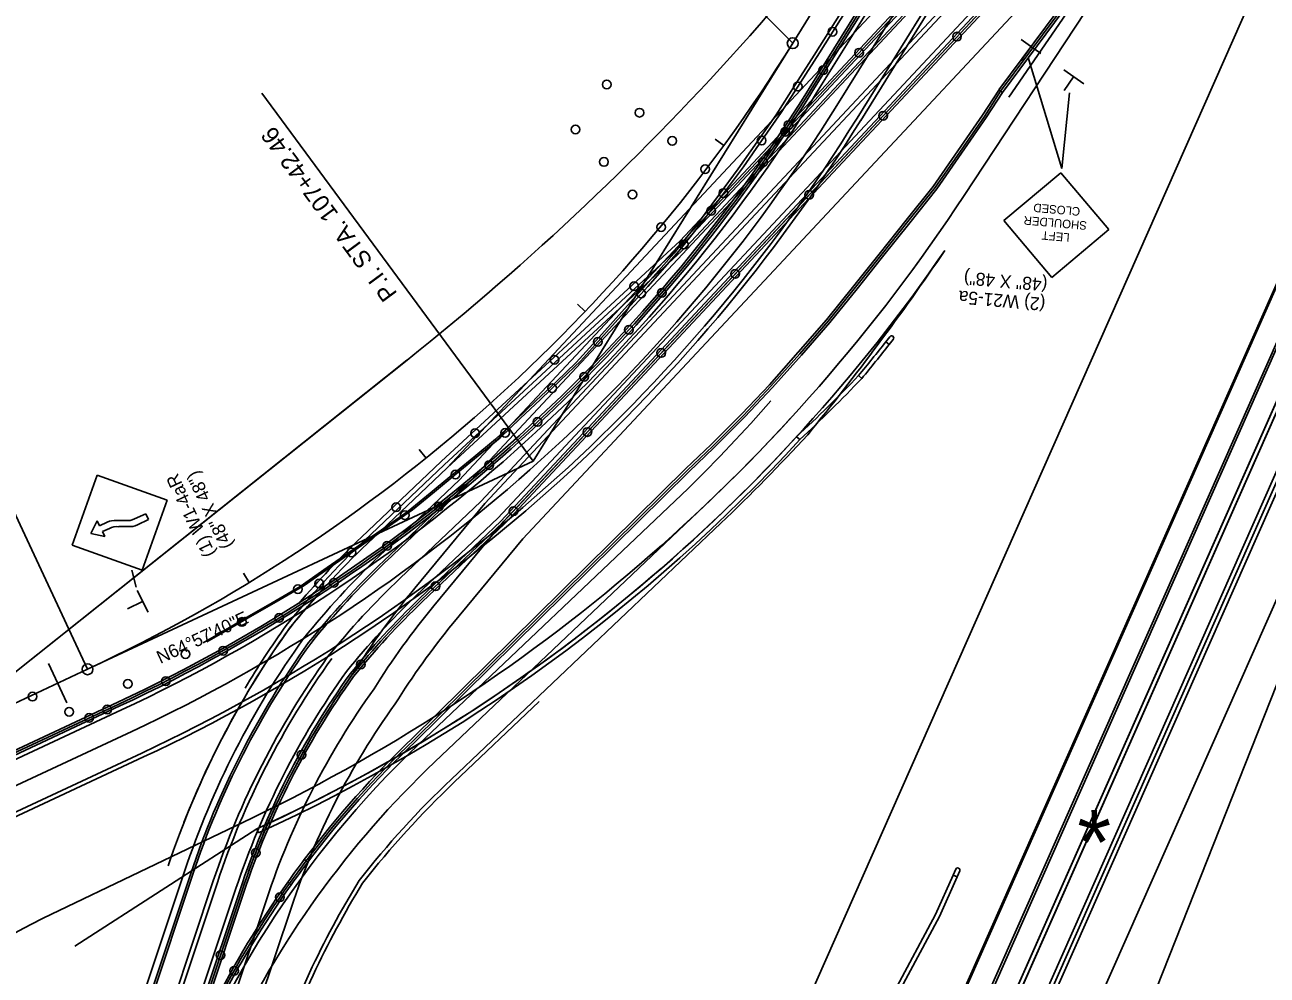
# Model space of a CAD drawing. Extents: x 659657 to 668193, y 633084 to 648639.
# Drawn here: x 661821 to 662395, y 642694 to 643133 of the extents above; entities that cross this region are included whole.
import ezdxf

# ---------------------------------------------------------------- set-up
doc = ezdxf.new("R2010")
doc.units = 0
for name, color, linetype in [('R_Border PE', 7, 'Continuous'), ('R_Border Prem', 7, 'Continuous'), ('R_Draft', 7, 'Continuous'), ('R_MOT_Stage 1', 7, 'Continuous'), ('R_MOT_Stage 1_Striping', 7, 'Continuous'), ('R_MOT_Stage 1A', 7, 'Continuous'), ('R_MOT_Stage 1B', 7, 'Continuous'), ('R_MOT_Stage 2', 7, 'Continuous'), ('R_MOT_Stage 2_Striping', 7, 'Continuous'), ('R_MOT_Stage 3', 7, 'Continuous'), ('R_MOT_Stage 3_Striping', 7, 'Continuous'), ('R_MOT_Stage 3_Striping_PPM', 7, 'Continuous'), ('R_MOT_Stage 4', 7, 'Continuous'), ('R_MOT_Stage 4_Striping', 7, 'Continuous'), ('R_MOT_Stage 4_Striping_PPM', 7, 'Continuous'), ('R_MOT_Stage 5_Striping_PPM', 7, 'Continuous'), ('S_EXISTING_ALIGNMENT', 7, 'Continuous'), ('T_SIGNAL CONTROL CABINET', 7, 'Continuous'), ('TEMP_SIGNAL_POLES_STAGE 2', 7, 'Continuous')]:
    doc.layers.add(name, color=color, linetype=linetype)

msp = doc.modelspace()

# ---------------------------------------------------------------- linework, layer by layer
at = {"layer": 'R_Border PE'}
for p, q in [((661854.33, 642925.37), (661842.73, 642893.02)), ((661886.69, 642913.79), (661854.33, 642925.37)), ((661886.69, 642913.79), (661875.09, 642881.43)), ((661871.6, 642905.1), (661876.74, 642907.53)), ((661878.03, 642904.79), (661876.74, 642907.53)), ((661851.35, 642898.39), (661854.36, 642904.27)), ((661855.44, 642901.99), (661854.36, 642904.27)), ((661855.44, 642901.99), (661858.91, 642903.63)), ((661863.21, 642904.37), (661867.28, 642904.39)), ((661864.27, 642901.63), (661868.57, 642901.65)), ((661872.89, 642902.36), (661878.03, 642904.79)), ((661857.8, 642896.98), (661851.35, 642898.39)), ((661856.73, 642899.25), (661859.97, 642900.78)), ((661857.8, 642896.98), (661856.73, 642899.25)), ((661875.09, 642881.43), (661842.73, 642893.02)), ((661870.33, 642881.46), (661872.27, 642873.57)), ((661872.84, 642872.12), (661877.86, 642862.05)), ((661875.19, 642867.04), (661868.32, 642863.6))]:
    msp.add_line(p, q, dxfattribs=at)
for centre, start, end in [((661862.28, 642896.9), 82.85062, 116.60852), ((661868.21, 642911.85), 262.85062, 296.60852), ((661869.52, 642909.09), 262.85062, 296.60852), ((661863.34, 642894.06), 82.85062, 116.60852)]:
    msp.add_arc(centre, 7.52, start, end, dxfattribs=at)
at = {"layer": 'R_Border Prem'}
for p, q in [((661686.79, 641562.92), (662861.91, 644217.67)), ((662241.56, 642722.34), (662249.66, 642740.62)), ((662243.39, 642721.53), (662251.49, 642739.82))]:
    msp.add_line(p, q, dxfattribs=at)
at = {"layer": 'R_Draft'}
for p, q in [((662281.01, 643126.57), (662290.2, 643120.09)), ((662285.49, 643123.21), (662281.06, 643116.94)), ((662299.84, 643067.06), (662284.29, 643118.32)), ((662300.79, 643112.62), (662309.99, 643106.14)), ((662305.27, 643109.27), (662300.85, 643102.99)), ((662299.84, 643067.06), (662303.38, 643101.98)), ((662273.12, 643042.93), (662299.43, 643065.05)), ((662299.43, 643065.05), (662321.58, 643038.75)), ((662273.12, 643042.93), (662295.26, 643016.61)), ((662295.26, 643016.61), (662321.58, 643038.75))]:
    msp.add_line(p, q, dxfattribs=at)
at = {"layer": 'R_MOT_Stage 1'}
for centre in [(662193.92, 643130.18), (662177.86, 643104.84), (662161.21, 643079.89), (662143.52, 643055.67), (662125.3, 643031.83), (662105.54, 643009.28), (662085.55, 642986.91), (662064.5, 642965.56), (662042.78, 642944.87), (662019.77, 642925.63), (661996.4, 642906.84), (661971.79, 642889.68), (661947.05, 642872.73), (661921.19, 642857.52), (661895.1, 642842.72), (661868.46, 642828.94), (661841.38, 642816.03)]:
    msp.add_circle(centre, 2, dxfattribs=at)
at = {"layer": 'R_MOT_Stage 1_Striping'}
for p, q in [((662175.55, 643124.86), (662368.1, 643434.97)), ((662055.71, 642931.85), (662175.55, 643124.86)), ((661849.86, 642835.69), (662055.71, 642931.85)), ((661661.48, 642747.69), (661849.86, 642835.69))]:
    msp.add_line(p, q, dxfattribs=at)
for points in [[(662175.55, 643124.86), (662034.06, 643266.21)], [(662055.71, 642931.85), (661930.36, 643101.87)], [(662139.71, 643080.61), (662143.75, 643077.66)], [(661849.86, 642835.69), (661765.22, 643016.9)], [(662076.09, 643004.4), (662079.71, 643000.95)], [(662003.06, 642937.15), (662006.2, 642933.25)], [(661921.88, 642880), (661924.49, 642875.73)], [(661831.8, 642838.29), (661840.26, 642820.17)]]:
    msp.add_lwpolyline(points, dxfattribs=at)
for centre in [(662175.55, 643124.86), (661849.86, 642835.69)]:
    msp.add_circle(centre, 2.5, dxfattribs=at)
msp.add_arc((661526.54, 643527.84), 763.94, 295.03892, 328.16324, dxfattribs=at)
at = {"layer": 'R_MOT_Stage 2'}
for p, q in [((662183.21, 643104.02), (662360.74, 643389.94)), ((662184.91, 643102.96), (662362.44, 643388.89)), ((662206.99, 643089.25), (662384.53, 643375.17)), ((662220.42, 642989.32), (662218.56, 642986.96)), ((662220.13, 642985.73), (662221.99, 642988.08)), ((662218.56, 642986.96), (662220.13, 642985.73)), ((662205.96, 642971.34), (662207.5, 642970.06)), ((662177.36, 642943.11), (662178.83, 642941.75)), ((661675.7, 642732.61), (661863.92, 642820.53)), ((661676.54, 642730.79), (661864.76, 642818.72)), ((661687.55, 642707.24), (661875.77, 642795.16)), ((661928.9, 642760.16), (661928.07, 642761.98)), ((662250.87, 642743.37), (662249.66, 642740.62)), ((662251.49, 642739.82), (662252.7, 642742.56))]:
    msp.add_line(p, q, dxfattribs=at)
for points in [[(662645.5, 643511.36), (661880.49, 641783.11), (661878.66, 641783.92), (662643.67, 643512.17)], [(662222.63, 642686.97), (662224.46, 642686.16), (662243.39, 642721.53), (662251.49, 642739.82), (662249.66, 642740.62), (662241.56, 642722.34)]]:
    msp.add_lwpolyline(points, close=True, dxfattribs=at)
for centre in [(662189.61, 643112.44), (662089.64, 643105.84), (662104.79, 643092.79), (662075.21, 643085.06), (662173.57, 643087.09), (662119.94, 643079.74), (662088.39, 643070.02), (662135.1, 643066.69), (662161.92, 643069.88), (662101.57, 643054.98), (662114.75, 643039.94), (662115.08, 643009.57), (662099.93, 642992.51), (662079.22, 642970.8), (662057.67, 642949.93), (662035.3, 642929.95), (662012.15, 642910.87), (661988.25, 642892.74), (661963.65, 642875.58), (661938.38, 642859.41), (661912.49, 642844.27), (661886.01, 642830.17), (661824.41, 642823.04), (661858.99, 642817.12), (661850.64, 642813.22)]:
    msp.add_circle(centre, 2, dxfattribs=at)
for centre, radius, start, end in [((661546.94, 643499.09), 748.94, 295.03892, 328.16324), ((661546.94, 643499.09), 750.94, 295.03892, 328.16324), ((661546.94, 643499.09), 776.94, 295.03892, 328.16324), ((662221.2, 642988.7), 1, 321.75487, 141.75487), ((661604.83, 643468.97), 780.38, 320.3806, 321.85467), ((661604.83, 643468.97), 782.38, 320.3806, 321.85467), ((661732.96, 643421.94), 653.27, 312.86404, 316.38904), ((661733.21, 643421.72), 654.94, 312.87496, 316.39996), ((661604.83, 643468.97), 777.38, 294.57008, 317.43245), ((661604.83, 643468.97), 779.38, 294.57008, 317.43245), ((662251.79, 642742.96), 1, 336.12343, 156.12343)]:
    msp.add_arc(centre, radius, start, end, dxfattribs=at)
at = {"layer": 'R_MOT_Stage 2_Striping'}
for p, q in [((662653.91, 643589.66), (661803.9, 641669.37)), ((661813.96, 641664.92), (662663.97, 643585.2)), ((662175.55, 643124.86), (662368.1, 643434.97)), ((662186.61, 643101.91), (662364.14, 643387.83)), ((662195.95, 643096.11), (662373.49, 643382.03)), ((662205.3, 643090.3), (662382.83, 643376.23)), ((662055.71, 642931.85), (662175.55, 643124.86)), ((661849.86, 642835.69), (662055.71, 642931.85)), ((661661.48, 642747.69), (661849.86, 642835.69)), ((661677.39, 642728.98), (661865.61, 642816.9)), ((661682.05, 642719.01), (661870.27, 642806.94)), ((661686.7, 642709.05), (661874.92, 642796.97)), ((661844.02, 642707.8), (661928.07, 642761.98))]:
    msp.add_line(p, q, dxfattribs=at)
for points in [[(661878.66, 641783.92), (662674.03, 643580.75)], [(662175.55, 643124.86), (662034.06, 643266.21)], [(662055.71, 642931.85), (661930.36, 643101.87)], [(662139.71, 643080.61), (662143.75, 643077.66)], [(661849.86, 642835.69), (661765.22, 643016.9)], [(662076.09, 643004.4), (662079.71, 643000.95)], [(662003.06, 642937.15), (662006.2, 642933.25)], [(661921.88, 642880), (661924.49, 642875.73)], [(661831.8, 642838.29), (661840.26, 642820.17)]]:
    msp.add_lwpolyline(points, dxfattribs=at)
for centre in [(662175.55, 643124.86), (661849.86, 642835.69)]:
    msp.add_circle(centre, 2.5, dxfattribs=at)
for centre, radius, start, end in [((661526.54, 643527.84), 763.94, 295.03892, 328.16324), ((661546.94, 643499.09), 752.94, 295.03892, 328.16324), ((661546.94, 643499.09), 763.94, 295.03892, 328.16324), ((661546.94, 643499.09), 774.94, 295.03892, 328.16324), ((661604.83, 643468.97), 777.38, 294.57008, 325.53986)]:
    msp.add_arc(centre, radius, start, end, dxfattribs=at)
at = {"layer": 'R_MOT_Stage 3'}
for p, q in [((662227.19, 642534.22), (662595.25, 643365.71)), ((662229.06, 642533.51), (662597.09, 643364.94)), ((662272.41, 643102.16), (662270.73, 643103.24)), ((661999.99, 642803.81), (662126.23, 642928.37)), ((662001.4, 642802.39), (662127.63, 642926.95)), ((662058.49, 642820.76), (662019.27, 642783.51)), ((661949.99, 642747.8), (661951.59, 642746.59)), ((661949.99, 642747.8), (661951.59, 642746.59)), ((662250.87, 642743.37), (662249.66, 642740.62)), ((662251.49, 642739.82), (662252.7, 642742.56)), ((661943.94, 642736.15), (661942.31, 642737.31))]:
    msp.add_line(p, q, dxfattribs=at)
for points in [[(662270.77, 643103.3), (662330.43, 643183.64)], [(662332.04, 643182.45), (662272.37, 643102.11)], [(662126.23, 642928.37), (662137.89, 642939.52), (662152.05, 642953.65), (662164.78, 642967.13), (662178.05, 642982.11), (662191.23, 642997.17), (662203.77, 643012.74), (662215.48, 643027.43), (662228, 643043.07), (662240.47, 643058.76), (662251.88, 643075.18), (662263.28, 643091.61), (662270.73, 643103.24)], [(662272.37, 643102.11), (662270.77, 643103.3)], [(662127.61, 642926.93), (662139.29, 642938.09), (662153.48, 642952.25), (662166.25, 642965.78), (662179.55, 642980.79), (662192.76, 642995.88), (662205.33, 643011.49), (662217.05, 643026.18), (662229.57, 643041.83), (662242.08, 643057.56), (662253.53, 643074.04), (662264.94, 643090.5), (662272.41, 643102.16)]]:
    msp.add_lwpolyline(points, dxfattribs=at)
msp.add_lwpolyline([(662222.63, 642686.97), (662224.46, 642686.16), (662243.39, 642721.53), (662251.49, 642739.82), (662249.66, 642740.62), (662241.56, 642722.34)], close=True, dxfattribs=at)
for centre in [(661938.68, 642730.35), (661917.56, 642696.4)]:
    msp.add_circle(centre, 2, dxfattribs=at)
for centre, radius, start, end in [((662313.83, 642473.36), 455.74, 133.52345, 142.9735), ((662313.83, 642473.36), 453.74, 133.52345, 142.9735), ((662313.83, 642473.36), 427.74, 133.52345, 141.97155), ((662313.83, 642473.36), 455.74, 142.9735, 144.60793), ((662313.83, 642473.36), 453.74, 142.9735, 144.60793), ((662251.79, 642742.96), 1, 336.12343, 156.12343), ((662313.83, 642473.36), 455.74, 144.60793, 161.54523), ((662313.83, 642473.36), 453.74, 144.60793, 161.54523), ((662339.24, 642514.77), 424.99, 148.49366, 161.49366)]:
    msp.add_arc(centre, radius, start, end, dxfattribs=at)
at = {"layer": 'R_MOT_Stage 3_Striping'}
for p, q in [((662215.01, 642538.82), (662583.35, 643370.94)), ((662225.31, 642534.93), (662593.4, 643366.49)), ((662127.26, 642919.17), (662002.75, 642800.91)), ((662134.84, 642911.19), (662010.32, 642792.93)), ((662142.41, 642903.22), (662017.9, 642784.96))]:
    msp.add_line(p, q, dxfattribs=at)
msp.add_lwpolyline([(662275.33, 643099.91), (662332.08, 643182.52)], dxfattribs=at)
for centre, radius, start, end in [((661218.38, 643727.23), 1242.16, 320.91191, 325.80422), ((661559.93, 643493.26), 807.12, 314.66076, 318.6137), ((661571.17, 643504.69), 818.51, 313.52345, 317.47639), ((661571.17, 643504.69), 829.51, 313.52345, 317.47639), ((662313.83, 642473.36), 451.74, 133.52345, 161.54523), ((662313.83, 642473.36), 440.74, 133.52345, 154.97155), ((662313.83, 642473.36), 429.74, 133.52345, 141.97155), ((662339.24, 642514.77), 426.97, 148.46317, 161.46317)]:
    msp.add_arc(centre, radius, start, end, dxfattribs=at)
at = {"layer": 'R_MOT_Stage 3_Striping_PPM'}
for p, q in [((661859, 641792.62), (662694.85, 643680.89)), ((661869.52, 641787.96), (662705.36, 643676.24)), ((661649.94, 642701.87), (661997.42, 642978.46))]:
    msp.add_line(p, q, dxfattribs=at)
msp.add_arc((661204.47, 643974.64), 1273.24, 308.51959, 328.16324, dxfattribs=at)
at = {"layer": 'R_MOT_Stage 4'}
for p, q in [((662123.59, 643033.62), (662260.12, 643179.66)), ((662125.01, 643032.2), (662261.56, 643178.27)), ((662040.8, 642904.05), (662280.53, 643160.49)), ((662042.22, 642902.64), (662281.99, 643159.13)), ((662123.59, 643033.62), (662013.23, 642931.66)), ((662125.01, 643032.2), (662014.58, 642930.18)), ((661976.35, 642896.66), (662013.19, 642931.62)), ((661977.72, 642895.21), (662014.58, 642930.18)), ((662003.24, 642868.42), (662040.8, 642904.05)), ((662004.62, 642866.97), (662042.22, 642902.64)), ((662250.87, 642743.37), (662249.66, 642740.62)), ((662251.49, 642739.82), (662252.7, 642742.56)), ((661838.7, 642489.27), (661920.29, 642733.77)), ((661840.6, 642488.63), (661922.19, 642733.14))]:
    msp.add_line(p, q, dxfattribs=at)
msp.add_lwpolyline([(662222.63, 642686.97), (662224.46, 642686.16), (662243.39, 642721.53), (662251.49, 642739.82), (662249.66, 642740.62), (662241.56, 642722.34)], close=True, dxfattribs=at)
for centre in [(662251.43, 643127.9), (662206.18, 643120.49), (662217.29, 643091.38), (662172.03, 643083.97), (662183.14, 643054.85), (662137.89, 643047.44), (662149, 643018.33), (662102.29, 643012.58), (662114.85, 642981.8), (662065.57, 642978.65), (662028.84, 642944.72), (662080.7, 642945.28), (661992.39, 642910.5), (662046.56, 642908.75), (661956.91, 642875.29), (662010.6, 642874.02), (661976.05, 642837.94), (661948.73, 642796.15), (661927.55, 642750.9), (661911.29, 642703.62)]:
    msp.add_circle(centre, 2, dxfattribs=at)
for centre, radius, start, end in [((662262.89, 642597.07), 414.56, 133.7271, 139.54429), ((662262.89, 642597.07), 412.56, 133.7271, 141.14019), ((662262.89, 642597.07), 375.56, 133.73749, 140.98375), ((662262.89, 642597.07), 373.56, 133.73812, 140.97442), ((662277.88, 642614.44), 413.97, 144.31525, 149.11223), ((662277.88, 642614.44), 376.97, 144.47113, 161.54523), ((662277.88, 642614.44), 374.97, 144.48043, 161.54523), ((662251.79, 642742.96), 1, 336.12343, 156.12343)]:
    msp.add_arc(centre, radius, start, end, dxfattribs=at)
at = {"layer": 'R_MOT_Stage 4_Striping'}
for p, q in [((662215.01, 642538.82), (662583.35, 643370.94)), ((662225.31, 642534.93), (662593.4, 643366.49)), ((662031.56, 642913.21), (662271.03, 643169.37)), ((662039.38, 642905.46), (662279.07, 643161.86)), ((661979.1, 642893.76), (662015.94, 642928.72)), ((661986.69, 642885.79), (662023.99, 642921.19)), ((661994.28, 642877.83), (662031.56, 642913.21)), ((662001.86, 642869.87), (662039.38, 642905.46)), ((661822.98, 642517.98), (661897.53, 642741.37)), ((661834.28, 642517.1), (661907.96, 642737.89)), ((661836.8, 642489.9), (661918.4, 642734.4))]:
    msp.add_line(p, q, dxfattribs=at)
msp.add_lwpolyline([(662015.94, 642928.72), (662126.42, 643030.78), (662263, 643176.88)], dxfattribs=at)
for centre, radius, start, end in [((662262.89, 642597.07), 410.56, 133.7271, 141.13245), ((662262.89, 642597.07), 399.56, 133.73022, 141.08853), ((662262.89, 642597.07), 388.56, 133.73347, 141.04211), ((662262.89, 642597.07), 377.56, 133.73686, 140.99299), ((662277.88, 642614.44), 411.97, 144.32296, 158.57296), ((662277.88, 642614.44), 400.97, 144.36674, 161.54523), ((662277.88, 642614.44), 389.97, 144.41299, 161.54523), ((662277.88, 642614.44), 378.97, 144.46193, 161.54523)]:
    msp.add_arc(centre, radius, start, end, dxfattribs=at)
at = {"layer": 'R_MOT_Stage 4_Striping_PPM'}
for p, q in [((661859, 641792.62), (662694.85, 643680.89)), ((661869.52, 641787.96), (662705.36, 643676.24)), ((661649.93, 642701.88), (661997.41, 642978.47))]:
    msp.add_line(p, q, dxfattribs=at)
msp.add_arc((661204.46, 643974.64), 1273.24, 308.51959, 328.16324, dxfattribs=at)
at = {"layer": 'R_MOT_Stage 5_Striping_PPM'}
for p, q in [((661859, 641792.62), (662694.85, 643680.89)), ((661869.52, 641787.96), (662705.36, 643676.24)), ((662215.01, 642538.82), (662716.34, 643671.38)), ((662125.58, 642250.33), (662543.15, 643193.66)), ((662015.9, 642928.67), (662254.92, 643184.34)), ((662024.66, 642920.47), (662263.68, 643176.15)), ((662033.43, 642912.28), (662272.45, 643167.95)), ((662042.19, 642904.08), (662281.21, 643159.76)), ((662050.96, 642895.89), (662289.98, 643151.56)), ((661634.41, 642689.5), (661997.42, 642978.46)), ((661979.1, 642893.76), (662015.9, 642928.67)), ((661987.87, 642885.56), (662024.66, 642920.47)), ((662325.04, 642641.64), (662435.5, 642920.82)), ((662033.43, 642912.28), (662001.07, 642873.22)), ((662042.19, 642904.08), (662009.84, 642865.02)), ((662050.96, 642895.89), (662018.6, 642856.83)), ((661849.53, 642594.37), (661898.48, 642741.05)), ((661860.91, 642590.57), (661909.86, 642737.25)), ((661865.89, 642529.68), (661932.63, 642729.66)), ((661872.29, 642586.77), (661921.24, 642733.45)), ((661882.48, 642541.47), (661944.01, 642725.86))]:
    msp.add_line(p, q, dxfattribs=at)
for centre, radius, start, end in [((661204.47, 643974.64), 1273.24, 308.51959, 328.16324), ((662263.34, 642596.7), 411.14, 133.73703, 141.14224), ((662263.34, 642596.7), 399.16, 133.64114, 141.04635), ((662292.43, 642632.16), 378.15, 140.39785, 147.8032), ((662292.43, 642632.16), 366.18, 140.51149, 147.91684), ((662292.43, 642632.16), 354.2, 140.63281, 148.03816), ((662277.88, 642614.44), 411.97, 144.33346, 161.54523), ((662277.88, 642614.44), 399.97, 144.33346, 161.54523), ((662277.88, 642614.44), 387.97, 144.33346, 161.54523), ((662277.88, 642614.44), 375.97, 144.33346, 161.54523), ((662277.88, 642614.44), 363.97, 144.33346, 161.54523), ((662277.88, 642614.44), 351.97, 144.33346, 161.54523)]:
    msp.add_arc(centre, radius, start, end, dxfattribs=at)
at = {"layer": 'S_EXISTING_ALIGNMENT'}
for p, q in [((662385.21, 643252.62), (662254.78, 643054.55)), ((661829.35, 642720.64), (661925.69, 642766.94))]:
    msp.add_line(p, q, dxfattribs=at)
for centre, radius, start, end in [((661571.17, 643504.69), 818.51, 295.66637, 326.63615), ((661937.25, 642496.11), 249.11, 115.66637, 161.54523)]:
    msp.add_arc(centre, radius, start, end, dxfattribs=at)
at = {"layer": 'T_SIGNAL CONTROL CABINET'}
for p, q in [((662361.59, 643389.42), (662184.06, 643103.49)), ((662271.57, 643102.7), (662331.23, 643183.05)), ((662021.56, 642923.02), (662260.84, 643178.96)), ((662041.51, 642903.35), (662281.26, 643159.81)), ((662000.69, 642803.1), (662126.93, 642927.66)), ((661984.62, 642887.97), (662021.69, 642923.14)), ((662003.93, 642867.69), (662041.51, 642903.35)), ((661864.34, 642819.62), (661676.12, 642731.7)), ((661943.13, 642736.73), (661950.79, 642747.19)), ((661842.83, 642586.93), (661894.68, 642742.32)), ((661849.17, 642517.48), (661921.24, 642733.45))]:
    msp.add_line(p, q, dxfattribs=at)
msp.add_lwpolyline([(662126.92, 642927.65), (662138.59, 642938.8), (662152.76, 642952.95), (662165.52, 642966.46), (662178.8, 642981.45), (662191.99, 642996.52), (662204.55, 643012.12), (662216.26, 643026.8), (662228.79, 643042.45), (662241.28, 643058.16), (662252.7, 643074.61), (662264.11, 643091.06), (662271.57, 643102.7)], dxfattribs=at)
for centre, radius, start, end in [((661546.94, 643499.09), 749.94, 295.03892, 328.16324), ((662262.89, 642597.07), 402.56, 133.73022, 141.10075), ((662262.89, 642597.07), 374.56, 133.73812, 140.9791), ((662277.88, 642614.44), 403.97, 144.35456, 161.54523), ((662277.88, 642614.44), 375.97, 144.47577, 161.54523), ((662313.83, 642473.36), 454.74, 133.52345, 142.9735), ((662313.83, 642473.36), 454.74, 144.60793, 161.54523)]:
    msp.add_arc(centre, radius, start, end, dxfattribs=at)
at = {"layer": 'TEMP_SIGNAL_POLES_STAGE 2'}
for points in [[(661905, 642848.32), (661911.11, 642851.87), (661924.01, 642859.37), (661936.92, 642866.87), (661949.9, 642874.41), (661962.43, 642883.15), (661974.9, 642891.85), (661987.37, 642900.54), (661999.9, 642909.28), (662010.05, 642917.63), (662020.15, 642925.94), (662030.24, 642934.25), (662040.4, 642942.6), (662049.75, 642951.51), (662059.05, 642960.36), (662068.34, 642969.22), (662077.7, 642978.13), (662086.99, 642988.46), (662096.22, 642998.72), (662105.45, 643008.99), (662108.59, 643012.48), (662123.01, 643028.84), (662134.36, 643043.08), (662143.57, 643055.44), (662152.79, 643067.8), (662161.51, 643080.32), (662170.25, 643092.85), (662179.08, 643106.68), (662187.89, 643120.49), (662194.98, 643131.73), (662202.06, 643142.96)], [(661903.25, 642847.87), (661909.37, 642851.42), (661922.27, 642858.92), (661935.18, 642866.42), (661948.09, 642873.92), (661960.55, 642882.62), (661973.02, 642891.31), (661985.49, 642900), (661997.95, 642908.7), (662008.05, 642917), (662018.14, 642925.31), (662028.24, 642933.61), (662038.33, 642941.92), (662047.63, 642950.78), (662056.93, 642959.63), (662066.23, 642968.49), (662075.53, 642977.35), (662084.76, 642987.62), (662094, 642997.88), (662103.23, 643008.15), (662106.36, 643011.63), (662120.74, 643027.95), (662132.04, 643042.13), (662141.23, 643054.46), (662150.43, 643066.8), (662159.14, 643079.29), (662167.85, 643091.78), (662176.65, 643105.58), (662185.46, 643119.38), (662192.55, 643130.62), (662199.64, 643141.85)]]:
    msp.add_lwpolyline(points, dxfattribs=at)

# ---------------------------------------------------------------- texts
at = {"layer": 'R_Border PE'}
for s, p in [('(1) W1-4aR', (661909.05, 642889.13)), ('(48" X 48")', (661917.19, 642892.97))]:
    msp.add_text(s, height=6, rotation=115.28351, dxfattribs=at).set_placement(p)
at = {"layer": 'R_Draft'}
for s, height, rotation, p in [('CLOSED', 3.94, 175.07636, (662308.46, 643049.03)), ('SHOULDER', 3.94, 175.07636, (662311.57, 643042.54)), ('LEFT', 3.94, 175.07677, (662303.59, 643037.01)), ('(48" X 48")', 6, 175.07779, (662293.39, 643016.14)), ('(2) W21-5a', 6, 175.07779, (662292.44, 643007.19))]:
    msp.add_text(s, height=height, rotation=rotation, dxfattribs=at).set_placement(p)
at = {"layer": 'R_MOT_Stage 1_Striping'}
for s, height, rotation, p in [('P.I. STA. 107+42.46', 8, 126.40017, (661993.2, 643009.26)), ('N64%%d57\'40"E', 6, 25.03892, (661883.53, 642838.07))]:
    msp.add_text(s, height=height, rotation=rotation, dxfattribs=at).set_placement(p)
at = {"layer": 'R_MOT_Stage 1A'}
msp.add_text('*', height=30, dxfattribs=at).set_placement((662306.99, 642740.75))
at = {"layer": 'R_MOT_Stage 1B'}
msp.add_text('*', height=30, dxfattribs=at).set_placement((662306.99, 642740.75))
at = {"layer": 'R_MOT_Stage 2_Striping'}
for s, height, rotation, p in [('P.I. STA. 107+42.46', 8, 126.40017, (661993.2, 643009.26)), ('N64%%d57\'40"E', 6, 25.03892, (661883.53, 642838.07))]:
    msp.add_text(s, height=height, rotation=rotation, dxfattribs=at).set_placement(p)

doc.saveas('drawing.dxf')
